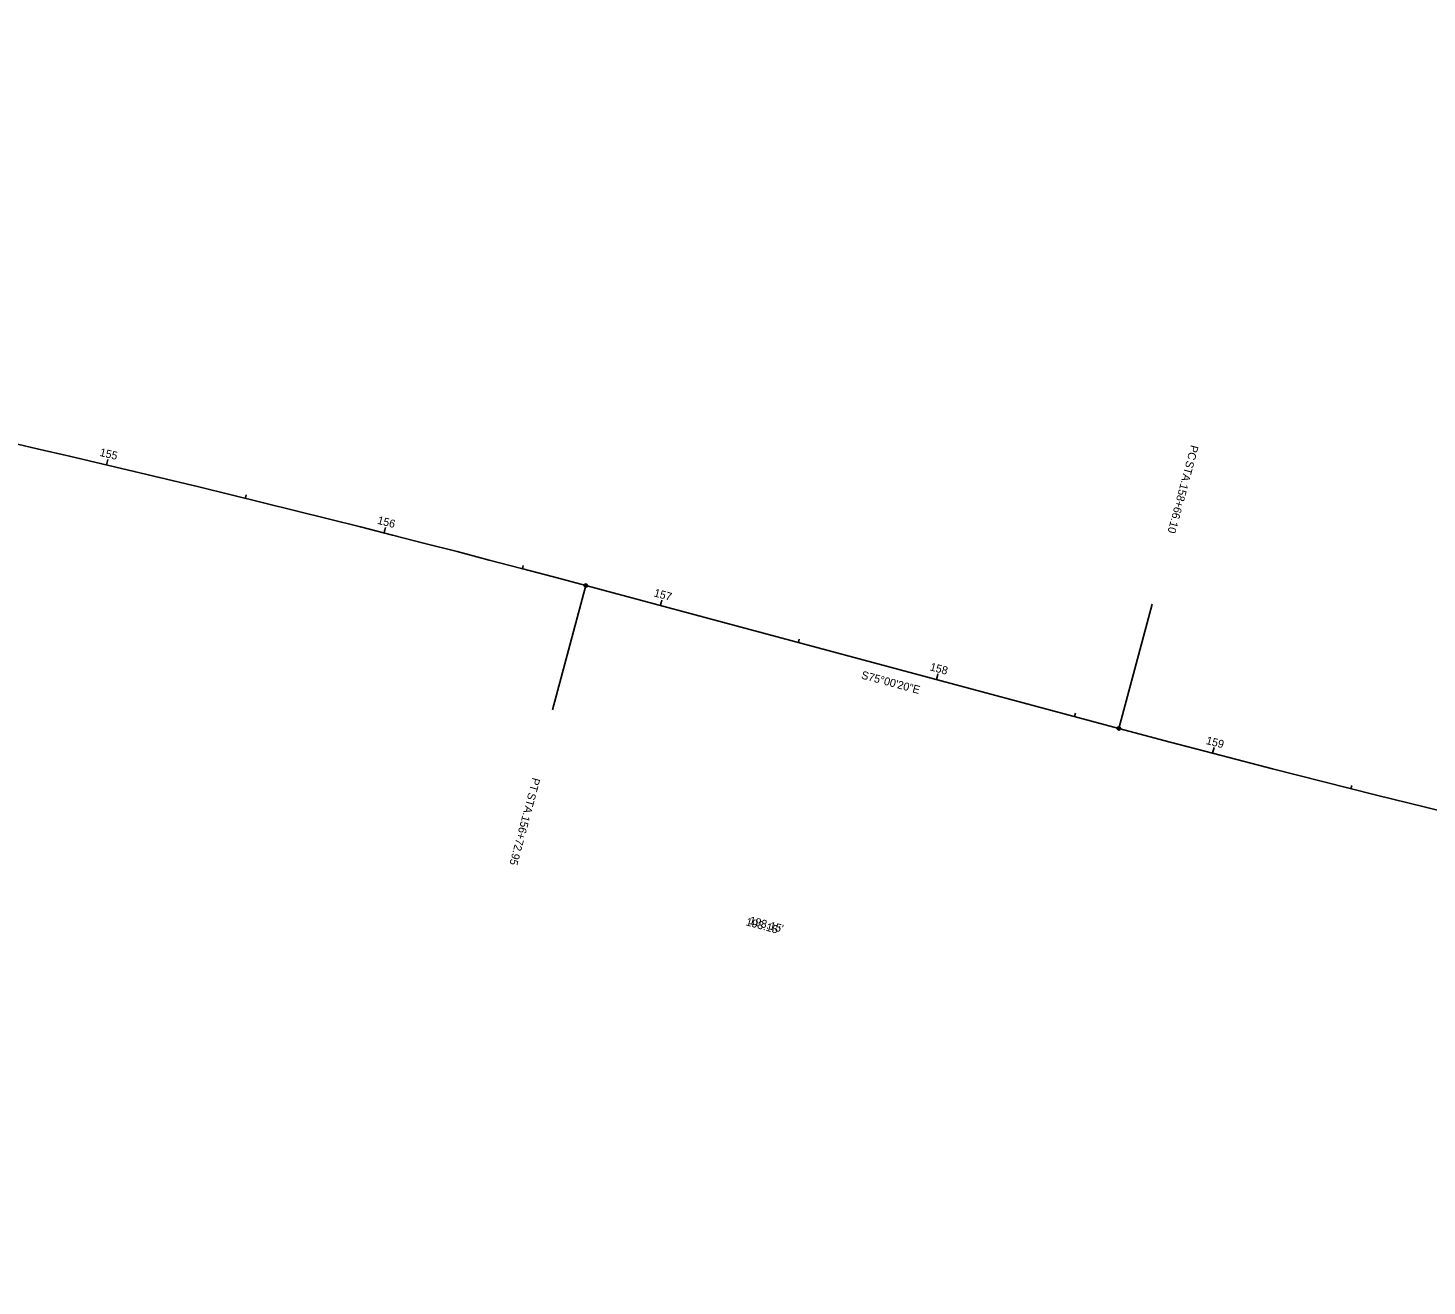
# Model space of a CAD drawing. Extents: x 1501024 to 1508874, y 327839 to 328839.
# Drawn here: x 1503488.2 to 1503977.7, y 328010.1 to 328450.2 of the extents above; entities that cross this region are included whole.
import ezdxf

# ---------------------------------------------------------------- set-up
doc = ezdxf.new("R2010")
doc.units = 0
for name, color, linetype in [('GE_X_Alignment', 7, 'Continuous'), ('GE_X_Alignment_100_Bearings', 7, 'Continuous'), ('GE_X_Alignment_100_Cardinal_Points', 7, 'Continuous'), ('GE_X_Alignment_100_Distances', 7, 'Continuous'), ('GE_X_Alignment_100_Stations', 7, 'Continuous'), ('GE_X_Alignment_500_Bearings', 7, 'Continuous'), ('GE_X_Alignment_500_Cardinal_Points', 7, 'Continuous'), ('GE_X_Alignment_500_Distances', 7, 'Continuous'), ('GE_X_Alignment_500_Stations', 7, 'Continuous')]:
    doc.layers.add(name, color=color, linetype=linetype)

msp = doc.modelspace()

# ---------------------------------------------------------------- linework, layer by layer
at = {"layer": 'GE_X_Alignment'}
msp.add_line((1503683.34, 328255.16), (1503869.91, 328205.19), dxfattribs=at)
for centre, start, end in [((1502200.96, 322720.66), 75.005634, 89.888968), ((1505352.29, 333739.68), 255.00563, 278.65563)]:
    msp.add_arc(centre, 5729.58, start, end, dxfattribs=at)
at = {"layer": 'GE_X_Alignment_100_Cardinal_Points'}
for p, q in [((1503683.34, 328255.16), (1503671.69, 328211.69)), ((1503869.91, 328205.19), (1503881.55, 328248.65))]:
    msp.add_line(p, q, dxfattribs=at)
for centre in [(1503683.34, 328255.16), (1503869.91, 328205.19)]:
    msp.add_circle(centre, 0.6, dxfattribs=at)
at = {"layer": 'GE_X_Alignment_100_Stations'}
for p, q in [((1503515.62, 328297.38), (1503516.08, 328299.32)), ((1503564.24, 328285.69), (1503564.52, 328286.86)), ((1503612.75, 328273.58), (1503613.24, 328275.52)), ((1503661.15, 328261.05), (1503661.46, 328262.21)), ((1503709.46, 328248.16), (1503709.98, 328250.09)), ((1503757.76, 328235.22), (1503758.07, 328236.38)), ((1503806.06, 328222.29), (1503806.57, 328224.22)), ((1503854.35, 328209.35), (1503854.67, 328210.51)), ((1503902.68, 328196.51), (1503903.18, 328198.45)), ((1503951.11, 328184.07), (1503951.4, 328185.24))]:
    msp.add_line(p, q, dxfattribs=at)
at = {"layer": 'GE_X_Alignment_500_Cardinal_Points'}
for p, q in [((1503683.34, 328255.16), (1503671.69, 328211.69)), ((1503869.91, 328205.19), (1503881.55, 328248.65))]:
    msp.add_line(p, q, dxfattribs=at)
for centre in [(1503683.34, 328255.16), (1503869.91, 328205.19)]:
    msp.add_circle(centre, 0.6, dxfattribs=at)
at = {"layer": 'GE_X_Alignment_500_Stations'}
for p, q in [((1503515.62, 328297.38), (1503516.08, 328299.32)), ((1503612.75, 328273.58), (1503613.04, 328274.75)), ((1503709.46, 328248.16), (1503709.77, 328249.32)), ((1503806.06, 328222.29), (1503806.37, 328223.45)), ((1503902.68, 328196.51), (1503902.98, 328197.67))]:
    msp.add_line(p, q, dxfattribs=at)

# ---------------------------------------------------------------- texts
at = {"layer": 'GE_X_Alignment_100_Bearings'}
msp.add_text('S75°00\'20"E', height=2.8, rotation=345.0056, dxfattribs=at).set_placement((1503779.55, 328222.66))
at = {"layer": 'GE_X_Alignment_100_Cardinal_Points'}
for s, p in [('PC', (1503895.1, 328304.52)), (' STA. ', (1503893.91, 328300.08)), ('158+66.10', (1503891.5, 328291.07)), ('PT', (1503664.74, 328188.13)), (' STA. ', (1503663.62, 328183.93)), ('156+72.95', (1503661.21, 328174.92))]:
    msp.add_text(s, height=2.8, rotation=255.0056, dxfattribs=at).set_placement(p)
at = {"layer": 'GE_X_Alignment_100_Distances'}
msp.add_text("193.15'", height=2.8, rotation=345.0056, dxfattribs=at).set_placement((1503740.32, 328136.82))
at = {"layer": 'GE_X_Alignment_100_Stations'}
for s, rotation, p in [('155', 346.7352, (1503513.07, 328300.55)), ('156', 345.7352, (1503610.21, 328276.81)), ('157', 345.0056, (1503706.98, 328251.41)), ('158', 345.0056, (1503803.56, 328225.54)), ('159', 345.3446, (1503900.19, 328199.75))]:
    msp.add_text(s, height=2.8, rotation=rotation, dxfattribs=at).set_placement(p)
at = {"layer": 'GE_X_Alignment_500_Bearings'}
msp.add_text('S75°00\'20"E', height=2.8, rotation=345.0056, dxfattribs=at).set_placement((1503779.55, 328222.66))
at = {"layer": 'GE_X_Alignment_500_Cardinal_Points'}
for s, p in [('PC', (1503895.1, 328304.52)), (' STA. ', (1503893.91, 328300.08)), ('158+66.10', (1503891.5, 328291.07)), ('PT', (1503664.74, 328188.13)), (' STA. ', (1503663.62, 328183.93)), ('156+72.95', (1503661.21, 328174.92))]:
    msp.add_text(s, height=2.8, rotation=255.0056, dxfattribs=at).set_placement(p)
at = {"layer": 'GE_X_Alignment_500_Distances'}
msp.add_text("193.15'", height=2.8, rotation=345.0056, dxfattribs=at).set_placement((1503739.15, 328136.35))
at = {"layer": 'GE_X_Alignment_500_Stations'}
msp.add_text('155', height=2.8, rotation=346.7352, dxfattribs=at).set_placement((1503513.07, 328300.55))

doc.saveas('drawing.dxf')
